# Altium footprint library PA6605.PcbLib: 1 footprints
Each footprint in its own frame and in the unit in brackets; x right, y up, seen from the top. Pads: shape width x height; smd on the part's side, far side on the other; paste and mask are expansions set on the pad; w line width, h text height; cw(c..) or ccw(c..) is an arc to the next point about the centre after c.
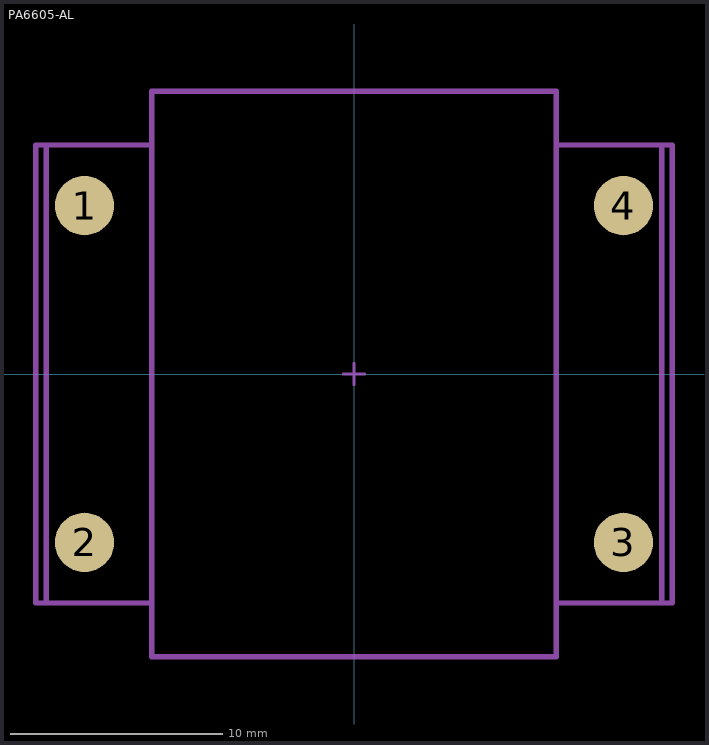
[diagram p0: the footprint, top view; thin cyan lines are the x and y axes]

## PA6605-AL [mil] "Transformer"
height 535
pads (4):
  round 110 smd: 1(-500,312.5) 2(-500,-312.5) 3(500,-312.5) 4(500,312.5)
M5 Assembly Top:
  lines w10: -570.87,-425 -570.87,425 ; -375.5,-425 -590.5,-425 -590.5,425 -375.5,425 ; 375.5,-425 590.5,-425 590.5,425 375.5,425 ; 570.87,-425 570.87,425 ; -375.5,-525 375.5,-525 375.5,525 -375.5,525 -375.5,-525
  text ".Designator" at -173.23,-649.61 h40
M15  Courtyards Top:
  lines w5: -20,0 0,0 ; 0,-20 0,0 ; 0,20 0,0 ; 20,0 0,0
3D body: height 427.5, standoff 418.5, extent 0,-425 570.86,425
3D body: height 327.5, standoff 318.5, extent 0,-370.08 570.86,425
3D body: height 187.5, standoff 178.5, extent 0,-370.08 559.06,370.08
3D body: height 227.5, standoff 218.5, extent 0,-370.08 555.12,370.08
3D body: height 148.5, standoff 138.5, extent -559.06,-370.08 0,370.08
3D body: height 188.5, standoff 177.5, extent -559.06,-370.08 0,370.08
3D body: height 352.5, standoff 343.5, extent -559.06,-370.08 0,370.08
3D body: height 247.5, standoff 238.5, extent -559.06,-370.08 0,370.08
3D body: height 287.5, standoff 278.5, extent -559.06,-370.08 559.06,370.08
3D body: height 392.5, standoff 383.5, extent -559.06,-370.08 0,370.08
3D body: height 100, standoff 0, extent -547.12,265.1 -452.5,359.91
3D body: height 100, standoff 0, extent 452.88,265.1 547.51,359.91
3D body: height 100, standoff 0, extent 452.88,-359.9 547.51,-265.09
3D body: height 100, standoff 0, extent -547.12,-359.9 -452.49,-265.09
3D body: height 535, standoff 10, extent -375.5,-525 375.5,525
3D body: height 138, standoff 100, extent -590.5,-425 -375.5,425
3D body: height 138, standoff 100, extent 375.5,-425 590.5,425
3D body: height 387.5, standoff 378.5, extent 0,-425 570.86,425
3D body: height 450, standoff 100, extent -532.24,280.07 -467.49,344.94
3D body: height 450, standoff 100, extent 467.76,280.07 532.51,344.94
3D body: height 450, standoff 100, extent 467.76,-344.93 532.51,-280.06
3D body: height 450, standoff 100, extent -532.24,-344.93 -467.49,-280.06
3D body: height 535.5, standoff 534, extent -347.63,447.49 -297.83,497.4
